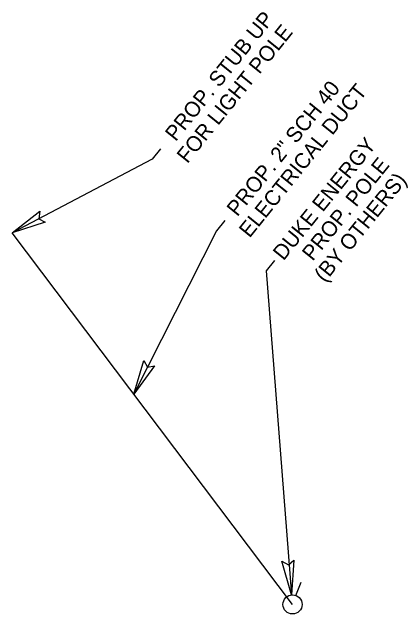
# Model space of a CAD drawing. Extents: x 1488620 to 1488724, y 499161 to 499318.
import ezdxf

# ---------------------------------------------------------------- set-up
doc = ezdxf.new("R2010")
doc.units = 0
for name, color, linetype in [('Default', 7, 'Continuous'), ('P Pole (Pow Co) CELL', 7, 'Continuous'), ('Prop Conduit _B', 7, 'Continuous')]:
    doc.layers.add(name, color=color, linetype=linetype)

msp = doc.modelspace()

# ---------------------------------------------------------------- linework, layer by layer
at = {"layer": 'Default'}
for p, q in [((1488659.29, 499282.64), (1488657.13, 499279.95)), ((1488657.13, 499279.95), (1488620.45, 499260.64)), ((1488676.13, 499263.86), (1488673.96, 499261.17)), ((1488673.96, 499261.17), (1488652.3, 499218.48)), ((1488689.13, 499253.37), (1488686.96, 499250.68)), ((1488686.96, 499250.68), (1488693.63, 499165.93))]:
    msp.add_line(p, q, dxfattribs=at)
for points in [[(1488629.13, 499263.46), (1488620.45, 499260.64), (1488627.71, 499266.27), (1488627.44, 499264.32)], [(1488657.76, 499225.81), (1488652.3, 499218.48), (1488654.97, 499227.28), (1488655.88, 499225.53)], [(1488694.25, 499175.04), (1488693.63, 499165.93), (1488691.11, 499174.76), (1488692.82, 499173.79)]]:
    msp.add_lwpolyline(points, close=True, dxfattribs=at)
at = {"layer": 'P Pole (Pow Co) CELL'}
msp.add_line((1488694.79, 499165.77), (1488696.14, 499169.27), dxfattribs=at)
msp.add_circle((1488693.89, 499163.44), 2.5, dxfattribs=at)
at = {"layer": 'Prop Conduit _B'}
msp.add_line((1488693.89, 499163.44), (1488620.45, 499260.64), dxfattribs=at)

# ---------------------------------------------------------------- texts
at = {"layer": 'Default'}
for s, p in [('PROP. STUB UP', (1488663.3, 499284.35)), ('FOR LIGHT POLE', (1488666.36, 499278.59)), ('PROP. 2" SCH 40', (1488679.43, 499264.7)), ('ELECTRICAL DUCT', (1488682.64, 499259.12)), ('DUKE ENERGY', (1488691.53, 499253.17)), ('PROP. POLE', (1488699.15, 499253.06)), ('(BY OTHERS)', (1488702.35, 499247.47))]:
    msp.add_text(s, height=4, rotation=51.1156, dxfattribs=at).set_placement(p)

doc.saveas('drawing.dxf')
